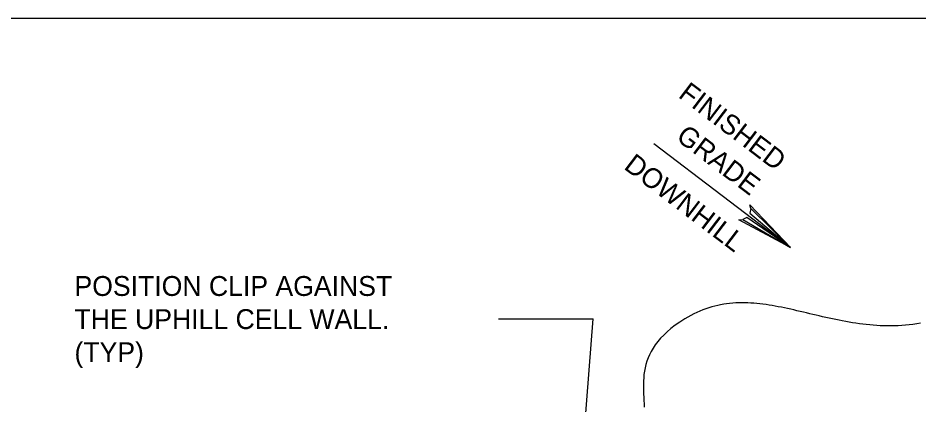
# Model space of a CAD drawing. Extents: x 638850 to 644908, y 297188 to 298900.
# Drawn here: x 639161 to 639297, y 297980.1 to 298038.5 of the extents above; entities that cross this region are included whole.
import ezdxf

# ---------------------------------------------------------------- set-up
doc = ezdxf.new("R2010")
doc.units = 0
for name, color, linetype in [('1', 7, 'Continuous'), ('2', 7, 'Continuous'), ('7', 7, 'Continuous')]:
    doc.layers.add(name, color=color, linetype=linetype)

msp = doc.modelspace()

# ---------------------------------------------------------------- linework, layer by layer
at = {"layer": '1'}
for p, q in [((638890.44, 298038.53), (639676.44, 298038.53)), ((639256.95, 298019.58), (639277.57, 298003.9)), ((639243.91, 297943.47), (639247.83, 297993.11))]:
    msp.add_line(p, q, dxfattribs=at)
msp.add_lwpolyline([(639271.59, 298009.76), (639271.47, 298009.09), (639277.57, 298003.9), (639271.59, 298009.76), (639271.47, 298010.31), (639277.57, 298003.9), (639270.97, 298008.42), (639270.38, 298008.13), (639277.57, 298003.9), (639269.78, 298008.08), (639270.38, 298008.13)], dxfattribs=at)
at = {"layer": '2'}
for points in [[(639297.2, 297992.47), (639296.63, 297992.36), (639296.06, 297992.28), (639295.5, 297992.21), (639294.95, 297992.16), (639294.39, 297992.11), (639293.84, 297992.08), (639293.28, 297992.05), (639292.74, 297992.05), (639292.2, 297992.05), (639291.66, 297992.05), (639291.12, 297992.08), (639290.6, 297992.1), (639290.05, 297992.15), (639289.53, 297992.19), (639289, 297992.24), (639288.48, 297992.3), (639287.97, 297992.36), (639287.45, 297992.44), (639286.93, 297992.52), (639286.42, 297992.61), (639285.92, 297992.7), (639285.4, 297992.8), (639284.91, 297992.89), (639284.4, 297992.99), (639283.91, 297993.11), (639283.41, 297993.21), (639282.92, 297993.32), (639282.43, 297993.43), (639281.93, 297993.54), (639281.45, 297993.66), (639280.96, 297993.77), (639280.48, 297993.89), (639280, 297994), (639279.52, 297994.12), (639279.04, 297994.23), (639278.56, 297994.34), (639278.09, 297994.45), (639277.62, 297994.55), (639277.14, 297994.66), (639276.68, 297994.75), (639276.2, 297994.85), (639275.74, 297994.94), (639275.27, 297995.03), (639274.81, 297995.11), (639274.35, 297995.19), (639273.89, 297995.27), (639273.42, 297995.33), (639272.96, 297995.37), (639272.51, 297995.42), (639272.05, 297995.46), (639271.58, 297995.5), (639271.13, 297995.51), (639270.67, 297995.53), (639270.22, 297995.53), (639269.76, 297995.53), (639269.31, 297995.51), (639268.86, 297995.48), (639268.4, 297995.43), (639267.95, 297995.39), (639267.51, 297995.31), (639267.04, 297995.23), (639266.6, 297995.14), (639266.15, 297995.03), (639265.7, 297994.92), (639265.25, 297994.79), (639264.79, 297994.63), (639264.34, 297994.46), (639263.91, 297994.29), (639263.46, 297994.09), (639263, 297993.88), (639262.55, 297993.64), (639262.1, 297993.38), (639261.65, 297993.12), (639261.65, 297993.12)], [(639261.65, 297993.12), (639260.9, 297992.62), (639260.19, 297992.15), (639259.55, 297991.65), (639258.98, 297991.16), (639258.46, 297990.66), (639257.98, 297990.17), (639257.56, 297989.67), (639257.18, 297989.18), (639256.85, 297988.68), (639256.55, 297988.19), (639256.31, 297987.7), (639256.09, 297987.21), (639255.91, 297986.7), (639255.77, 297986.2), (639255.64, 297985.7), (639255.55, 297985.21), (639255.47, 297984.72), (639255.43, 297984.22), (639255.4, 297983.73), (639255.38, 297983.23), (639255.38, 297982.74), (639255.4, 297982.24), (639255.41, 297981.75), (639255.43, 297981.27), (639255.46, 297980.78), (639255.49, 297980.3), (639255.51, 297979.8)]]:
    msp.add_lwpolyline(points, dxfattribs=at)
at = {"layer": '7'}
msp.add_line((639233.53, 297993.11), (639247.83, 297993.11), dxfattribs=at)

# ---------------------------------------------------------------- texts
at = {"layer": '1'}
for s, p in [('FINISHED', (639260.51, 298026.66)), ('GRADE', (639260.15, 298020.24)), ('DOWNHILL', (639252.29, 298015.86))]:
    msp.add_text(s, height=3, rotation=322.7554, dxfattribs=at).set_placement(p)
for s, p in [('POSITION CLIP AGAINST', (639169.56, 297996.57)), ('THE UPHILL CELL WALL.', (639169.56, 297991.57)), ('(TYP)', (639169.56, 297986.57))]:
    msp.add_text(s, height=3, dxfattribs=at).set_placement(p)

doc.saveas('drawing.dxf')
